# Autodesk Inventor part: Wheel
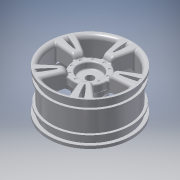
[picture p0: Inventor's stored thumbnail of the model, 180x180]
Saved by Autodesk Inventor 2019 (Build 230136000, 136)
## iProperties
Shininess: 54.0
Length Units: 11272
Angle Units: 11279
Time Units: 11290
Mass Units: 11286
Length Display Precision: 4
Angle Display Precision: 2
Compacted: True
Company: Autodesk
Created: 2000-05
Part Number: Wheel
Project: Inventor Samples
User Status: IN PROGRESS
Document SubType Name: Modeling
Designer: Autodesk, Inc.
Density: 2.71 g/cm^3
Material: Aluminum-6061
Mass: 26.0183 g
Surface Area: 145.445 cm^2
Volume: 9.60086 cm^3
Appearance: Light Grey
Density: 0.0
Volumn: 0.0
Area: 0.0
PropertySet Name: Model Information
Control State: 0
Master: False
Checked Out: False
Checked Out Date: 2018-05-30
Last Check In Date: 2018-05-30
Author: Autodesk, Inc.
Revision Number: A
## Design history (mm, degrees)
node "Revolution1" dims "d2" = 90 deg
  sketch "Sketch2"
    geometry: L1 (-26.543, 0)-(0, 0); L2 (0, 0)-(0, 25.971); L3 (0, 25.971)-(-26.543, 25.971); L4 (-26.543, 0)-(-26.543, 25.971); L5 (-31.852, 0)-(5.309, 0) reference; 1 further point
    constraints: 8 end point, 2 parallel, 1 collinear, 1 horizontal, 1 perpendicular, 1 point on line
    dimensions: "d0" = 51.943 diameter of L3 L1; "d1" = 26.543 distance between parallel lines of L4 L2
node "Revolution2" dims "d6" = 90 deg
  sketch "Sketch3"
    geometry: L1 (-31.852, 0)-(5.309, 0) reference; L2 (0, -25.971)-(0, 25.971) reference; L3 (-26.543, 25.971)-(0, 25.971) reference; L4 (-1.778, 25.971)-(-1.778, 23.94); L5 (-1.778, 23.94)-(-24.765, 23.94); L6 (-24.765, 23.94)-(-24.765, 25.971); L7 (-26.543, -25.971)-(-26.543, 25.971) reference
    constraints: 6 end point, 2 perpendicular, 2 point on line, 1 parallel
    dimensions: "d3" = 47.879 diameter of L5 L1; "d4" = 1.778 distance between parallel lines of L2 L4; "d5" = 1.778 distance between parallel lines of L6 L7 (= d4)
node "Revolution3" dims "d12" = 90 deg
  sketch "Sketch4"
    geometry: L1 (-24.765, 23.94)-(-1.778, 23.94) reference; L2 (0, -25.971)-(0, 25.971) reference; L3 (-26.543, -25.971)-(-26.543, 25.971) reference; L4 (-31.852, 0)-(5.309, 0) reference; L5 (-20.701, 23.94)-(-20.701, 25.4); L6 (-20.701, 25.4)-(-19.558, 25.4); L7 (-19.558, 25.4)-(-19.558, 23.94); L8 (-6.985, 23.94)-(-6.985, 25.4); L9 (-6.985, 25.4)-(-5.842, 25.4); L10 (-5.842, 25.4)-(-5.842, 23.94)
    constraints: 12 end point, 4 perpendicular, 4 point on line, 2 parallel, 1 collinear
    dimensions: "d7" = 1.143 distance between parallel lines of L7 L5 (= d8); "d8" = 1.143 distance between parallel lines of L10 L8; "d9" = 6.985 distance between parallel lines of L2 L8; "d10" = 6.985 distance between parallel lines of L3 L7; "d11" = 50.8 diameter of L9.end L4
node "Extrusion1" dims "d14" = 11.811, "d15" = 0
  sketch "Sketch5"
    geometry: C1 r 25.971 at (0, 0) reference; C2 r 22.86 at (0, 0)
    constraints: 1 centre point, 1 coincident
    dimensions: "d13" = 45.72 diameter of C2
node "Extrusion2" dims "d17" = 11.811, "d18" = 0
  sketch "Sketch6"
    geometry: C1 r 22.86 at (0, 0) reference; C2 r 8.382 at (0, 0)
    constraints: 1 centre point, 1 coincident
    dimensions: "d16" = 16.764 diameter of C2
node "Extrusion3" dims "d19" = 6.731, "d20" = 0
  sketch "Sketch7"
    geometry: C1 r 8.382 at (0, 0) reference
node "Fillet4" dims "d40" = 2.54
node "Extrusion5" dims "d46" = 8.89 (computed from d19), "d47" = 0
  sketch "Sketch10"
    geometry: L1 (0, 0)-(0, 25.971); L2 (-6.072, 24.664)-(-2.989, 11.822); L3 (6.072, 24.664)-(2.989, 11.822); A1 r 25.4 centre (0, 0) between (1.27, 25.368) and (-1.27, 25.368) reference; A2 r 57.15 centre (-55.876, 24.699) between (0, 12.7) and (1.27, 25.368); A3 r 57.15 centre (55.876, 24.699) between (-1.27, 25.368) and (0, 12.7); A4 r 8.382 centre (0, 0) between (-4.859, 6.83) and (4.859, 6.83) reference; A5 r 4.763 centre (-7.62, 10.71) between (-4.859, 6.83) and (-2.989, 11.822); A6 r 4.763 centre (7.62, 10.71) between (2.989, 11.822) and (4.859, 6.83); 1 further point
    constraints: 14 point on circle, 6 end point, 4 centre point, 4 tangent, 3 horizontal alignment, 2 equal radius, 1 point on line, 1 vertical, 1 vertical alignment, 1 other
    dimensions: "d41" = 12.7 distance of A2.start point (0, 0); "d42" = 2.54 distance of A1.start A1.end; "d43" = 57.15 radius of A2; "d44" = 27 deg angle of L3 L2; "d45" = 4.7625 radius of A5; "d51" = 15.24 distance of A6.centre A5.centre
node "Fillet6" dims "d59" = 0.39687
node "Circular Pattern2" dims "d48" = 50 (= Spokes), "d50" = 360 deg
node "Revolution5" dims "d53" = 90 deg
  sketch "Sketch11"
    geometry: L1 (-24.765, 23.906)-(-20.701, 23.906) reference; L2 (-19.558, 23.94)-(-6.985, 23.94) reference; L3 (-20.701, 25.4)-(-19.558, 25.4) reference; L4 (-26.543, 25.971)-(-24.765, 25.971) reference; L5 (-26.543, 25.971)-(-26.543, 27.241); L6 (-26.543, 27.241)-(-6.985, 27.242); L7 (-6.985, 27.242)-(-6.985, 23.94); L8 (-19.558, 25.4)-(-19.558, 23.94); L9 (-20.701, 25.4)-(-20.701, 23.906); L10 (-24.765, 25.971)-(-24.765, 23.906); L11 (-30.455, 0)-(-3.073, 0) reference
    constraints: 12 end point, 4 parallel, 2 perpendicular
    dimensions: "d52" = 1.27 distance of L4.start L5.end
node "Revolution6" dims "d57" = 90 deg
  sketch "Sketch12"
    geometry: L1 (-26.543, -25.971)-(-26.543, 25.971) reference; L2 (-19.812, 8.382)-(-26.543, 8.382) reference; L3 (-28.689, 0)-(-17.974, 0) reference; L4 (-19.812, 0)-(-19.812, 8.382); L5 (-23.645, 10.172)-(-21.261, 9.963); A1 r 3.175 centre (-23.368, 13.335) between (-26.543, 13.335) and (-23.645, 10.172); A2 r 1.587 centre (-21.399, 8.382) between (-19.812, 8.382) and (-21.261, 9.963)
    constraints: 4 end point, 4 point on circle, 4 tangent, 2 centre point, 2 point on line, 1 perpendicular
    dimensions: "d54" = 3.175 radius of A1; "d55" = 1.5875 radius of A2; "d56" = 85 deg angle of L4 L5
node "Fillet5" dims "d58" = 5.08
workaxis "Work Axis2"
workplane "Work Plane3"
  workpoint "Work Point3"
  workpoint "Work Point4"
  workpoint "Work Point5"
node "Revolution8" dims "d97" = 90 deg
  sketch "Sketch17"
    geometry: L1 (-1.449, 9.963)-(-3.833, 10.172) reference; L2 (0, 6.732)-(-3.833, 7.067); L3 (25.121, 0)-(-12.045, 0) reference; L4 (-3.833, 7.067)-(-3.833, 10.641); L5 (-3.833, 10.641)-(1.27, 10.641); L6 (1.27, 10.641)-(1.27, 6.732); L7 (1.27, 6.732)-(0, 6.732); L8 (0, -2.511)-(0, 6.732) reference; A1 r 1.587 centre (-1.588, 8.382) between (0, 8.382) and (-1.449, 9.963) reference
    constraints: 10 end point, 3 parallel, 2 perpendicular
    dimensions: "d93" = 1.27 distance between parallel lines of L6 L8
node "Fillet14" dims "d100" = 1.5875
node "Fillet15" dims "d101" = 1.5875
node "Fillet16" dims "d102" = 0.8128
node "Fillet17" dims "d103" = 0.8128
node "Fillet18" dims "d104" = 0.8128
node "Extrusion7" dims "d71" = 5.08, "d72" = 0
  sketch "Sketch14"
    geometry: L1 (-6.032, 3.483)-(-6.032, -3.483); L2 (-6.032, -3.483)-(0, -6.966); L3 (0, -6.966)-(6.032, -3.483); L4 (6.032, -3.483)-(6.032, 3.483); L5 (6.032, 3.483)-(0, 6.966); L6 (0, 6.966)-(-6.032, 3.483); C1 r 8.382 at (0, 0) reference; C2 r 6.032 at (0, 0)
    constraints: 12 end point, 6 tangent, 4 equal length, 2 vertical, 1 centre point, 1 coincident
    dimensions: "d70" = 12.065 distance between parallel lines of L4 L1
node "Fillet9" dims "d73" = 3.175
node "Extrusion8" dims "d79" = 25.4, "d80" = 0
  sketch "Sketch15"
    geometry: L1 (-3.285, 13.055)-(-4.738, 19.106) reference; L2 (-2.989, 11.822)-(-3.285, 13.055) reference; L3 (4.738, 19.106)-(3.285, 13.055) reference; L4 (2.989, 11.822)-(3.285, 13.055) reference; L5 (0, 0)-(-4.166, 22.477); L6 (0, 0)-(4.166, 22.477); L7 (-2.911, 22.674)-(-1.198, 13.431); L8 (1.198, 13.431)-(2.911, 22.674); L9 (0, 0)-(0, 13.652); C1 r 25.971 at (0, 0) reference; A1 r 22.86 centre (0, 0) between (-4.166, 22.477) and (4.166, 22.477) reference; A2 r 57.15 centre (55.876, 24.699) between (-1.051, 19.657) and (-0.391, 14.691) reference; A3 r 57.15 centre (-55.876, 24.699) between (0.391, 14.691) and (1.051, 19.657) reference; A4 r 1.218 centre (0, 13.652) between (-1.198, 13.431) and (1.198, 13.431); A5 r 2.488 centre (0, 13.652) between (-2.446, 13.199) and (2.446, 13.199); 4 further points
    constraints: 10 end point, 8 point on circle, 2 centre point, 2 parallel, 2 point on line, 2 tangent, 1 concentric, 1 vertical
    dimensions: "d74" = 1.27 distance between parallel lines of L7 L5; "d75" = 1.27 distance between parallel lines of L6 L8 (= d74); "d76" = 13.6525 distance of A1.centre L9.end; "d77" = 21 deg angle of L8 L7; "d78" = 1.27 radial gap between concentric circles of A4 A5 (= d75)
node "Circular Pattern3" dims "d81" = 50 (= Spokes), "d83" = 360 deg
node "Extrusion6" dims "d68" = 2.159, "d69" = 0
  sketch "Sketch13"
    geometry: C1 r 2.381 at (0, 0); C2 r 23.94 at (0, 0) reference
    constraints: 1 centre point, 1 concentric
    dimensions: "d67" = 4.7625 diameter of C1
workplane "Work Plane4"
node "Extrusion9" dims "d108" = 25.4, "d109" = 20 deg
  sketch "Sketch18" dims "d106" = 17.78
    geometry: L1 (0, 36.36)-(0, -36.36) reference; C1 r 2.381 at (0, 0) reference; C2 r 0.635 at (0, 8.89); 1 further point
    constraints: 1 centre point, 1 coincident, 1 point on line, 1 vertical alignment, 2 other
    dimensions: "d107" = 1.27 diameter of C2
node "Fillet19" dims "d110" = 0.127
node "Circular Pattern4" dims "d111" = 100, "d113" = 360 deg
node "Fillet20" dims "d114" = 0.8128
node "Fillet21" dims "d115" = 0.8128
node "Fillet22" dims "d116" = 0.8128
body "Solid1"
other parameters: "d95" = 5 deg (derived), "d96" = 22.88399 (derived), "d105" = -0.381
